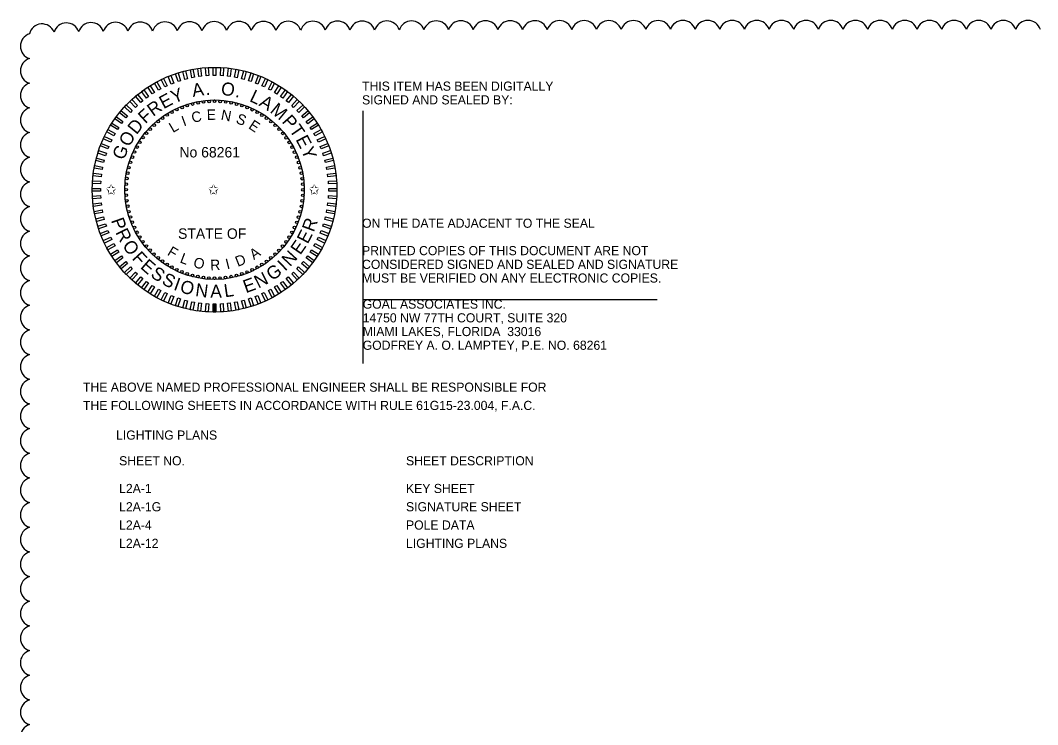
# Model space of a CAD drawing. Extents: x -811 to 10319, y -2309 to 9962.
# Drawn here: x -810.98 to -803.18, y -2279.1 to -2273.71 of the extents above; entities that cross this region are included whole.
import ezdxf

# ---------------------------------------------------------------- set-up
doc = ezdxf.new("R2010")
doc.units = 0
for name, color, linetype in [('AdhocPoint_dp', 7, 'Continuous'), ('PlotBorder_dp', 7, 'Continuous'), ('ScratchEle_dp', 7, 'Continuous'), ('TextMinor', 7, 'Continuous'), ('TextMisc', 7, 'Continuous'), ('TextShtNo', 7, 'Continuous')]:
    doc.layers.add(name, color=color, linetype=linetype)

msp = doc.modelspace()

# ---------------------------------------------------------------- linework, layer by layer
at = {"layer": 'AdhocPoint_dp'}
for p, q in [((-808.3546, -2274.4022), (-808.3546, -2276.337)), ((-808.3546, -2275.847), (-806.0979, -2275.847))]:
    msp.add_line(p, q, dxfattribs=at)
at = {"layer": 'ScratchEle_dp'}
for centre, radius, start, end in [((-810.0588, -2273.8204), 0.0991, 17.94243, 162.94243), ((-809.8699, -2273.819), 0.0991, 17.8789, 162.8789), ((-809.6809, -2273.8179), 0.0991, 17.83076, 162.83076), ((-809.4919, -2273.8168), 0.0991, 17.79266, 162.79266), ((-809.3029, -2273.8159), 0.0991, 17.76151, 162.76151), ((-809.1139, -2273.8151), 0.0991, 17.73544, 162.73544), ((-808.9249, -2273.8144), 0.0991, 17.7132, 162.7132), ((-808.736, -2273.8137), 0.0991, 17.69393, 162.69393), ((-808.547, -2273.8131), 0.0991, 17.67702, 162.67702), ((-808.358, -2273.8125), 0.0991, 17.66204, 162.66204), ((-808.169, -2273.812), 0.0991, 17.64863, 162.64863), ((-807.98, -2273.8115), 0.0991, 17.63655, 162.63655), ((-807.791, -2273.8111), 0.0991, 17.62558, 162.62558), ((-807.602, -2273.8107), 0.0991, 17.61556, 162.61556), ((-807.413, -2273.8104), 0.0991, 17.60637, 162.60637), ((-807.224, -2273.81), 0.0991, 17.5979, 162.5979), ((-807.035, -2273.8097), 0.0991, 17.59006, 162.59006), ((-806.846, -2273.8094), 0.0991, 17.58277, 162.58277), ((-806.657, -2273.8092), 0.0991, 17.57597, 162.57597), ((-806.468, -2273.8089), 0.0991, 17.56961, 162.56961), ((-806.279, -2273.8087), 0.0991, 17.56364, 162.56364), ((-806.09, -2273.8085), 0.0991, 17.55803, 162.55803), ((-805.901, -2273.8083), 0.0991, 17.55274, 162.55274), ((-805.712, -2273.8082), 0.0991, 17.54774, 162.54774), ((-805.523, -2273.808), 0.0991, 17.54301, 162.54301), ((-805.334, -2273.8079), 0.0991, 17.53852, 162.53852), ((-805.145, -2273.8077), 0.0991, 17.53425, 162.53425), ((-804.956, -2273.8076), 0.0991, 17.53018, 162.53018), ((-804.767, -2273.8075), 0.0991, 17.52631, 162.52631), ((-804.578, -2273.8075), 0.0991, 17.52261, 162.52261), ((-804.389, -2273.8074), 0.0991, 17.51907, 162.51907), ((-804.2, -2273.8073), 0.0991, 17.51569, 162.51569), ((-804.011, -2273.8073), 0.0991, 17.51244, 162.51244), ((-803.822, -2273.8073), 0.0991, 17.50933, 162.50933), ((-803.633, -2273.8072), 0.0991, 17.50633, 162.50633), ((-803.444, -2273.8072), 0.0991, 17.50345, 162.50345), ((-803.2551, -2273.8072), 0.0991, 17.50077, 162.50077), ((-810.8128, -2273.8348), 0.0992, 21.52097, 166.52097), ((-810.6255, -2273.8267), 0.0991, 18.44241, 163.44241), ((-810.4367, -2273.824), 0.0991, 18.17187, 163.17187), ((-810.2478, -2273.822), 0.0991, 18.03188, 163.03188), ((-810.8794, -2273.9061), 0.099, 107.5, 252.5), ((-810.8794, -2274.095), 0.0991, 107.5, 252.5), ((-810.8794, -2274.2841), 0.0991, 107.5, 252.5), ((-810.8794, -2274.4731), 0.0991, 107.5, 252.5), ((-810.8794, -2274.6621), 0.0991, 107.5, 252.5), ((-810.8794, -2274.8511), 0.0991, 107.5, 252.5), ((-810.8794, -2275.0401), 0.0991, 107.5, 252.5), ((-810.8794, -2275.2291), 0.0991, 107.5, 252.5), ((-810.8794, -2275.4181), 0.0991, 107.5, 252.5), ((-810.8794, -2275.6071), 0.0991, 107.5, 252.5), ((-810.8794, -2275.7961), 0.0991, 107.5, 252.5), ((-810.8794, -2275.9851), 0.0991, 107.5, 252.5), ((-810.8794, -2276.1741), 0.0991, 107.5, 252.5), ((-810.8794, -2276.3631), 0.0991, 107.5, 252.5), ((-810.8794, -2276.5521), 0.0991, 107.5, 252.5), ((-810.8794, -2276.7411), 0.0991, 107.5, 252.5), ((-810.8794, -2276.9301), 0.0991, 107.5, 252.5), ((-810.8794, -2277.1191), 0.0991, 107.5, 252.5), ((-810.8794, -2277.3081), 0.0991, 107.5, 252.5), ((-810.8794, -2277.4971), 0.0991, 107.5, 252.5), ((-810.8794, -2277.6861), 0.0991, 107.5, 252.5), ((-810.8794, -2277.8751), 0.0991, 107.5, 252.5), ((-810.8794, -2278.0641), 0.0991, 107.5, 252.5), ((-810.8794, -2278.2531), 0.0991, 107.5, 252.5), ((-810.8794, -2278.4421), 0.0991, 107.50047, 252.50047), ((-810.8794, -2278.6311), 0.0991, 107.52584, 252.52584), ((-810.8792, -2278.82), 0.0991, 107.56719, 252.56719), ((-810.8789, -2279.009), 0.0991, 107.61129, 252.61129), ((-810.8785, -2279.198), 0.0991, 107.65843, 252.65843)]:
    msp.add_arc(centre, radius, start, end, dxfattribs=at)
at = {"layer": 'TextMinor'}
for radius in [0.9375, 0.6875]:
    msp.add_circle((-809.4901, -2275.0057), radius, dxfattribs=at)
at = {"layer": 'TextShtNo'}
for p, q in [((-809.5001, -2275.9432), (-809.5003, -2275.8807)), ((-809.4901, -2275.9432), (-809.4903, -2275.8807)), ((-809.4801, -2275.9431), (-809.4803, -2275.8806))]:
    msp.add_line(p, q, dxfattribs=at)
for points in [[(-809.7508, -2274.1703), (-809.77, -2274.1765), (-809.7893, -2274.1172), (-809.7701, -2274.1109)], [(-809.6979, -2274.1556), (-809.7174, -2274.1606), (-809.7329, -2274.1001), (-809.7134, -2274.0951)], [(-809.6441, -2274.1442), (-809.6639, -2274.148), (-809.6756, -2274.0867), (-809.6558, -2274.0829)], [(-809.5897, -2274.1362), (-809.6097, -2274.1388), (-809.6175, -2274.0768), (-809.5975, -2274.0743)], [(-809.5349, -2274.1317), (-809.555, -2274.133), (-809.559, -2274.0707), (-809.5388, -2274.0694)], [(-809.4799, -2274.1306), (-809.5001, -2274.1306), (-809.5001, -2274.0682), (-809.4799, -2274.0682)], [(-809.425, -2274.133), (-809.4452, -2274.1317), (-809.4412, -2274.0694), (-809.4211, -2274.0707)], [(-809.3703, -2274.1388), (-809.3904, -2274.1363), (-809.3825, -2274.0743), (-809.3625, -2274.0768)], [(-809.3161, -2274.148), (-809.336, -2274.1442), (-809.3243, -2274.0829), (-809.3044, -2274.0867)], [(-809.2626, -2274.1606), (-809.2822, -2274.1556), (-809.2667, -2274.0951), (-809.2471, -2274.1002)], [(-809.21, -2274.1766), (-809.2292, -2274.1704), (-809.2099, -2274.111), (-809.1907, -2274.1172)], [(-809.9027, -2274.2339), (-809.9204, -2274.2437), (-809.9505, -2274.189), (-809.9328, -2274.1792)], [(-809.8535, -2274.2096), (-809.8717, -2274.2182), (-809.8983, -2274.1617), (-809.8801, -2274.1531)], [(-809.8028, -2274.1883), (-809.8215, -2274.1957), (-809.8445, -2274.1377), (-809.8258, -2274.1303)], [(-809.1585, -2274.1958), (-809.1773, -2274.1884), (-809.1543, -2274.1303), (-809.1355, -2274.1378)], [(-809.1083, -2274.2182), (-809.1266, -2274.2096), (-809.1, -2274.1531), (-809.0817, -2274.1617)], [(-809.0596, -2274.2438), (-809.0773, -2274.234), (-809.0473, -2274.1793), (-809.0296, -2274.189)], [(-809.9962, -2274.2917), (-810.0125, -2274.3036), (-810.0492, -2274.2531), (-810.0329, -2274.2412)], [(-809.9504, -2274.2614), (-809.9674, -2274.2722), (-810.0009, -2274.2195), (-809.9838, -2274.2087)], [(-809.0127, -2274.2723), (-809.0297, -2274.2615), (-808.9962, -2274.2088), (-808.9792, -2274.2196)], [(-808.9675, -2274.3037), (-808.9839, -2274.2919), (-808.9472, -2274.2413), (-808.9308, -2274.2532)], [(-810.0817, -2274.3608), (-810.0964, -2274.3746), (-810.1391, -2274.3291), (-810.1244, -2274.3153)], [(-810.04, -2274.3249), (-810.0556, -2274.3378), (-810.0954, -2274.2897), (-810.0798, -2274.2768)], [(-808.9245, -2274.3379), (-808.9401, -2274.3251), (-808.9003, -2274.2769), (-808.8847, -2274.2898)], [(-808.8837, -2274.3748), (-808.8984, -2274.3609), (-808.8557, -2274.3154), (-808.8409, -2274.3292)], [(-810.1578, -2274.44), (-810.1707, -2274.4556), (-810.2188, -2274.4158), (-810.206, -2274.4002)], [(-810.121, -2274.3992), (-810.1348, -2274.4139), (-810.1803, -2274.3712), (-810.1665, -2274.3565)], [(-808.8453, -2274.4141), (-808.8591, -2274.3994), (-808.8136, -2274.3566), (-808.7998, -2274.3713)], [(-808.8094, -2274.4557), (-808.8223, -2274.4402), (-808.7742, -2274.4004), (-808.7613, -2274.4159)], [(-810.2235, -2274.5282), (-810.2343, -2274.5452), (-810.287, -2274.5118), (-810.2762, -2274.4947)], [(-810.192, -2274.4831), (-810.2039, -2274.4994), (-810.2544, -2274.4627), (-810.2426, -2274.4464)], [(-808.7762, -2274.4996), (-808.7881, -2274.4832), (-808.7376, -2274.4465), (-808.7257, -2274.4629)], [(-808.7458, -2274.5454), (-808.7567, -2274.5283), (-808.7039, -2274.4949), (-808.6931, -2274.5119)], [(-810.252, -2274.5752), (-810.2617, -2274.5929), (-810.3164, -2274.5628), (-810.3067, -2274.5451)], [(-808.7184, -2274.593), (-808.7281, -2274.5753), (-808.6734, -2274.5453), (-808.6637, -2274.5629)], [(-810.3, -2274.6741), (-810.3074, -2274.6928), (-810.3654, -2274.6698), (-810.358, -2274.6511)], [(-810.2775, -2274.6239), (-810.2861, -2274.6421), (-810.3426, -2274.6155), (-810.334, -2274.5973)], [(-808.694, -2274.6423), (-808.7026, -2274.624), (-808.6461, -2274.5974), (-808.6375, -2274.6157)], [(-808.6728, -2274.693), (-808.6802, -2274.6742), (-808.6222, -2274.6512), (-808.6147, -2274.67)], [(-810.3192, -2274.7256), (-810.3254, -2274.7448), (-810.3848, -2274.7255), (-810.3786, -2274.7063)], [(-808.6548, -2274.7449), (-808.661, -2274.7257), (-808.6016, -2274.7064), (-808.5954, -2274.7256)], [(-810.3351, -2274.7782), (-810.3401, -2274.7977), (-810.4006, -2274.7822), (-810.3956, -2274.7626)], [(-808.64, -2274.7979), (-808.6451, -2274.7784), (-808.5846, -2274.7628), (-808.5796, -2274.7824)], [(-810.357, -2274.8859), (-810.3595, -2274.9059), (-810.4214, -2274.8981), (-810.4189, -2274.878)], [(-810.3477, -2274.8317), (-810.3515, -2274.8515), (-810.4129, -2274.8398), (-810.4091, -2274.82)], [(-808.6287, -2274.8517), (-808.6325, -2274.8319), (-808.5711, -2274.8202), (-808.5673, -2274.84)], [(-808.6207, -2274.9061), (-808.6232, -2274.8861), (-808.5613, -2274.8782), (-808.5588, -2274.8983)], [(-810.3628, -2274.9405), (-810.364, -2274.9607), (-810.4264, -2274.9568), (-810.4251, -2274.9366)], [(-808.6162, -2274.9609), (-808.6174, -2274.9407), (-808.5551, -2274.9368), (-808.5539, -2274.957)], [(-810.3651, -2274.9955), (-810.3651, -2275.0156), (-810.4276, -2275.0156), (-810.4276, -2274.9955)], [(-808.6151, -2275.0158), (-808.6151, -2274.9957), (-808.5526, -2274.9957), (-808.5526, -2275.0158)], [(-810.3641, -2275.0504), (-810.3628, -2275.0706), (-810.4251, -2275.0745), (-810.4264, -2275.0543)], [(-810.3595, -2275.1052), (-810.357, -2275.1252), (-810.4189, -2275.1331), (-810.4215, -2275.113)], [(-808.6233, -2275.1254), (-808.6207, -2275.1054), (-808.5588, -2275.1132), (-808.5613, -2275.1333)], [(-808.6175, -2275.0708), (-808.6162, -2275.0506), (-808.5539, -2275.0545), (-808.5551, -2275.0747)], [(-810.3516, -2275.1596), (-810.3478, -2275.1794), (-810.4091, -2275.1911), (-810.4129, -2275.1713)], [(-808.6325, -2275.1796), (-808.6287, -2275.1598), (-808.5674, -2275.1715), (-808.5712, -2275.1913)], [(-810.3402, -2275.2134), (-810.3352, -2275.2329), (-810.3956, -2275.2485), (-810.4007, -2275.2289)], [(-810.3255, -2275.2664), (-810.3192, -2275.2856), (-810.3786, -2275.3049), (-810.3849, -2275.2857)], [(-808.6611, -2275.2857), (-808.6548, -2275.2665), (-808.5954, -2275.2858), (-808.6017, -2275.305)], [(-808.6451, -2275.2331), (-808.6401, -2275.2136), (-808.5796, -2275.2291), (-808.5846, -2275.2487)], [(-810.3074, -2275.3183), (-810.3, -2275.3371), (-810.3581, -2275.3601), (-810.3655, -2275.3413)], [(-808.6803, -2275.3372), (-808.6729, -2275.3185), (-808.6148, -2275.3415), (-808.6222, -2275.3602)], [(-810.2862, -2275.369), (-810.2776, -2275.3873), (-810.3341, -2275.4139), (-810.3427, -2275.3956)], [(-810.2618, -2275.4183), (-810.2521, -2275.436), (-810.3068, -2275.466), (-810.3165, -2275.4484)], [(-808.7282, -2275.4361), (-808.7185, -2275.4184), (-808.6638, -2275.4485), (-808.6735, -2275.4662)], [(-808.7027, -2275.3874), (-808.6941, -2275.3692), (-808.6376, -2275.3958), (-808.6462, -2275.414)], [(-810.2344, -2275.4659), (-810.2236, -2275.483), (-810.2763, -2275.5164), (-810.2871, -2275.4994)], [(-810.204, -2275.5117), (-810.1922, -2275.5281), (-810.2427, -2275.5648), (-810.2545, -2275.5484)], [(-808.7882, -2275.5282), (-808.7763, -2275.5119), (-808.7258, -2275.5486), (-808.7377, -2275.5649)], [(-808.7568, -2275.4831), (-808.7459, -2275.4661), (-808.6932, -2275.4995), (-808.704, -2275.5166)], [(-810.1708, -2275.5556), (-810.158, -2275.5711), (-810.2061, -2275.6109), (-810.2189, -2275.5954)], [(-808.8224, -2275.5713), (-808.8095, -2275.5557), (-808.7614, -2275.5955), (-808.7743, -2275.6111)], [(-810.135, -2275.5972), (-810.1211, -2275.6119), (-810.1667, -2275.6547), (-810.1805, -2275.64)], [(-810.0965, -2275.6365), (-810.0818, -2275.6504), (-810.1246, -2275.6959), (-810.1393, -2275.6821)], [(-808.8985, -2275.6505), (-808.8838, -2275.6367), (-808.8411, -2275.6822), (-808.8558, -2275.696)], [(-808.8592, -2275.6121), (-808.8454, -2275.5974), (-808.7999, -2275.6401), (-808.8137, -2275.6548)], [(-810.0557, -2275.6734), (-810.0402, -2275.6862), (-810.08, -2275.7344), (-810.0955, -2275.7215)], [(-810.0127, -2275.7076), (-809.9964, -2275.7194), (-810.0331, -2275.77), (-810.0494, -2275.7581)], [(-809.9676, -2275.739), (-809.9505, -2275.7498), (-809.984, -2275.8025), (-810.001, -2275.7917)], [(-809.0299, -2275.7499), (-809.0128, -2275.7391), (-808.9794, -2275.7918), (-808.9964, -2275.8026)], [(-808.984, -2275.7196), (-808.9677, -2275.7077), (-808.931, -2275.7582), (-808.9473, -2275.7701)], [(-808.9402, -2275.6864), (-808.9246, -2275.6735), (-808.8848, -2275.7216), (-808.9004, -2275.7345)], [(-809.9206, -2275.7675), (-809.9029, -2275.7773), (-809.933, -2275.832), (-809.9507, -2275.8223)], [(-809.8719, -2275.7931), (-809.8536, -2275.8017), (-809.8802, -2275.8582), (-809.8985, -2275.8496)], [(-809.8217, -2275.8155), (-809.8029, -2275.8229), (-809.8259, -2275.881), (-809.8447, -2275.8735)], [(-809.1775, -2275.823), (-809.1587, -2275.8156), (-809.1357, -2275.8736), (-809.1545, -2275.881)], [(-809.1268, -2275.8017), (-809.1085, -2275.7931), (-809.0819, -2275.8496), (-809.1002, -2275.8582)], [(-809.0775, -2275.7774), (-809.0598, -2275.7676), (-809.0297, -2275.8223), (-809.0474, -2275.8321)], [(-809.7702, -2275.8347), (-809.751, -2275.8409), (-809.7703, -2275.9003), (-809.7895, -2275.8941)], [(-809.7176, -2275.8507), (-809.698, -2275.8557), (-809.7136, -2275.9162), (-809.7331, -2275.9111)], [(-809.6641, -2275.8633), (-809.6443, -2275.8671), (-809.656, -2275.9284), (-809.6758, -2275.9246)], [(-809.6099, -2275.8725), (-809.5899, -2275.875), (-809.5977, -2275.937), (-809.6177, -2275.9345)], [(-809.5552, -2275.8783), (-809.5351, -2275.8796), (-809.539, -2275.9419), (-809.5591, -2275.9406)], [(-809.5003, -2275.8807), (-809.4801, -2275.8807), (-809.4801, -2275.9431), (-809.5003, -2275.9431)], [(-809.4453, -2275.8796), (-809.4252, -2275.8783), (-809.4213, -2275.9406), (-809.4414, -2275.9419)], [(-809.3906, -2275.8751), (-809.3705, -2275.8725), (-809.3627, -2275.9345), (-809.3827, -2275.937)], [(-809.3362, -2275.8671), (-809.3163, -2275.8633), (-809.3046, -2275.9246), (-809.3245, -2275.9284)], [(-809.2824, -2275.8557), (-809.2628, -2275.8507), (-809.2473, -2275.9112), (-809.2668, -2275.9162)], [(-809.2294, -2275.841), (-809.2102, -2275.8348), (-809.1909, -2275.8941), (-809.2101, -2275.9004)]]:
    msp.add_lwpolyline(points, close=True, dxfattribs=at)
for centre in [(-809.6581, -2274.3493), (-809.6165, -2274.3401), (-809.5745, -2274.3335), (-809.5321, -2274.3295), (-809.4896, -2274.3282), (-809.447, -2274.3296), (-809.4046, -2274.3336), (-809.3626, -2274.3403), (-809.3211, -2274.3496), (-809.8526, -2274.4333), (-809.816, -2274.4117), (-809.7781, -2274.3924), (-809.739, -2274.3755), (-809.6989, -2274.3612), (-809.2802, -2274.3615), (-809.2402, -2274.376), (-809.2012, -2274.3929), (-809.1633, -2274.4123), (-809.1266, -2274.4339), (-809.9535, -2274.5114), (-809.9215, -2274.4833), (-809.8879, -2274.4572), (-809.0915, -2274.4579), (-809.0578, -2274.484), (-809.0259, -2274.5122), (-810.0118, -2274.5734), (-809.9836, -2274.5415), (-808.9959, -2274.5423), (-808.9678, -2274.5742), (-810.0618, -2274.6422), (-810.0379, -2274.607), (-808.9417, -2274.6079), (-808.9178, -2274.6431), (-810.1029, -2274.7167), (-810.0835, -2274.6788), (-808.8962, -2274.6798), (-808.8769, -2274.7177), (-810.1343, -2274.7958), (-810.1198, -2274.7557), (-808.86, -2274.7568), (-808.8456, -2274.7968), (-810.1555, -2274.8782), (-810.1462, -2274.8366), (-808.8338, -2274.8377), (-808.8245, -2274.8793), (-810.1662, -2274.9625), (-810.1622, -2274.9202), (-808.8179, -2274.9213), (-808.814, -2274.9637), (-810.1676, -2275.0051), (-810.1663, -2275.0476), (-808.814, -2275.0488), (-808.8126, -2275.0062), (-810.1623, -2275.09), (-810.1557, -2275.132), (-808.8248, -2275.1331), (-808.8181, -2275.0911), (-810.1464, -2275.1736), (-808.8341, -2275.1747), (-810.1346, -2275.2145), (-810.1202, -2275.2545), (-808.8604, -2275.2556), (-808.846, -2275.2155), (-810.1033, -2275.2936), (-810.0841, -2275.3315), (-810.0624, -2275.3682), (-808.9184, -2275.3691), (-808.8967, -2275.3325), (-808.8774, -2275.2946), (-810.0385, -2275.4034), (-810.0125, -2275.4371), (-808.9685, -2275.4379), (-808.9424, -2275.4043), (-809.9844, -2275.469), (-809.9543, -2275.4991), (-809.0268, -2275.4999), (-808.9967, -2275.4698), (-809.9224, -2275.5273), (-809.8888, -2275.5534), (-809.8536, -2275.5774), (-809.817, -2275.599), (-809.1642, -2275.5996), (-809.1276, -2275.578), (-809.0924, -2275.5541), (-809.0587, -2275.528), (-809.7791, -2275.6184), (-809.74, -2275.6353), (-809.7, -2275.6498), (-809.6591, -2275.6617), (-809.6176, -2275.671), (-809.5756, -2275.6777), (-809.5332, -2275.6817), (-809.4481, -2275.6818), (-809.4058, -2275.6778), (-809.3637, -2275.6712), (-809.3222, -2275.662), (-809.2813, -2275.6501), (-809.2412, -2275.6358), (-809.2022, -2275.6189), (-809.4901, -2275.6832)]:
    msp.add_circle(centre, 0.01, dxfattribs=at)

# ---------------------------------------------------------------- texts
at = {"layer": 'PlotBorder_dp'}
for s, p in [('THIS ITEM HAS BEEN DIGITALLY', (-808.3596, -2274.2471)), ('SIGNED AND SEALED BY:', (-808.3596, -2274.3521)), ('ON THE DATE ADJACENT TO THE SEAL', (-808.3596, -2275.2971)), ('PRINTED COPIES OF THIS DOCUMENT ARE NOT ', (-808.3596, -2275.5071)), ('CONSIDERED SIGNED AND SEALED AND SIGNATURE ', (-808.3596, -2275.6121)), ('MUST BE VERIFIED ON ANY ELECTRONIC COPIES.', (-808.3596, -2275.7171)), ('GOAL ASSOCIATES INC.', (-808.3546, -2275.917)), ('14750 NW 77TH COURT, SUITE 320', (-808.3546, -2276.022)), ('MIAMI LAKES, FLORIDA  33016', (-808.3546, -2276.127)), ('GODFREY A. O. LAMPTEY, P.E. NO. 68261', (-808.3546, -2276.232)), ('THE ABOVE NAMED PROFESSIONAL ENGINEER SHALL BE RESPONSIBLE FOR ', (-810.4987, -2276.5531)), ('THE FOLLOWING SHEETS IN ACCORDANCE WITH RULE 61G15-23.004, F.A.C.', (-810.4987, -2276.6931)), ('LIGHTING PLANS', (-810.245, -2276.9201))]:
    msp.add_text(s, height=0.07, dxfattribs=at).set_placement(p)
at = {"layer": 'TextMisc'}
for s, p in [('SHEET NO.', (-810.2215, -2277.1171)), ('SHEET DESCRIPTION', (-808.0226, -2277.1171)), ('L2A-1', (-810.2215, -2277.3293)), ('KEY SHEET', (-808.0226, -2277.3293)), ('L2A-1G', (-810.2215, -2277.4693)), ('SIGNATURE SHEET', (-808.0226, -2277.4693)), ('L2A-4', (-810.2215, -2277.6093)), ('POLE DATA', (-808.0226, -2277.6093)), ('L2A-12', (-810.2215, -2277.7493)), ('LIGHTING PLANS', (-808.0226, -2277.7493))]:
    msp.add_text(s, height=0.07, dxfattribs=at).set_placement(p)
at = {"layer": 'TextShtNo'}
for s, height, rotation, p in [('A', 0.1, 8.80884, (-809.6551, -2274.295)), ('O', 0.1, 352.18771, (-809.4449, -2274.2775)), ('E', 0.1, 28.10553, (-809.8806, -2274.3895)), ('Y', 0.1, 21.06329, (-809.8021, -2274.3462)), ('.', 0.1, 1.04184, (-809.5575, -2274.2793)), ('L', 0.1, 334.67271, (-809.2279, -2274.3249)), ('R', 0.1, 35.92688, (-809.9609, -2274.4483)), ('.', 0.1, 343.52684, (-809.3358, -2274.2926)), ('A', 0.1, 328.40959, (-809.1552, -2274.3576)), ('M', 0.1, 320.6426, (-809.0707, -2274.4088)), ('F', 0.1, 42.37723, (-810.0205, -2274.5047)), ('C', 0.08, 12.20255, (-809.6579, -2274.494)), ('E', 0.08, 0.41861, (-809.5498, -2274.4706)), ('N', 0.08, 349.29143, (-809.4455, -2274.4691)), ('D', 0.1, 50.8569, (-810.0885, -2274.5884)), ('L', 0.08, 30.40215, (-809.8093, -2274.572)), ('I', 0.08, 20.01168, (-809.7258, -2274.5216)), ('S', 0.08, 337.02207, (-809.3325, -2274.4909)), ('E', 0.08, 325.86633, (-809.2358, -2274.5311)), ('P', 0.1, 311.19658, (-808.9784, -2274.4857)), ('T', 0.1, 304.45632, (-808.9209, -2274.5494)), ('O', 0.1, 59.51777, (-810.1446, -2274.6833)), ('E', 0.1, 297.63152, (-808.8707, -2274.6202)), ('G', 0.1, 68.0518, (-810.1851, -2274.784)), ('Y', 0.1, 290.58928, (-808.8281, -2274.6991)), ('P', 0.1, 289.40551, (-810.2848, -2275.2402)), ('R', 0.1, 69.5134, (-808.7299, -2275.3354)), ('R', 0.1, 296.14576, (-810.2518, -2275.3319)), ('E', 0.1, 62.47116, (-808.7761, -2275.4261)), ('O', 0.1, 303.96711, (-810.2003, -2275.4325)), ('E', 0.1, 55.42892, (-808.833, -2275.5104)), ('F', 0.1, 312.62798, (-810.1279, -2275.5346)), ('F', 0.08, 328.72408, (-809.8582, -2275.5022)), ('L', 0.08, 339.29159, (-809.7609, -2275.5613)), ('D', 0.08, 22.01279, (-809.312, -2275.5976)), ('A', 0.08, 34.49917, (-809.1883, -2275.5451)), ('N', 0.1, 47.17876, (-808.9123, -2275.5995)), ('E', 0.1, 319.07833, (-810.0645, -2275.6029)), ('O', 0.08, 349.68206, (-809.6562, -2275.601)), ('R', 0.08, 2.33977, (-809.5217, -2275.623)), ('I', 0.08, 14.20366, (-809.3941, -2275.6163)), ('G', 0.1, 35.11153, (-809.0492, -2275.7072)), ('I', 0.1, 43.64556, (-808.9499, -2275.634)), ('S', 0.1, 326.12056, (-809.9869, -2275.6688)), ('S', 0.1, 333.193, (-809.9015, -2275.7249)), ('N', 0.1, 26.86136, (-809.1544, -2275.7632)), ('I', 0.1, 340.26543, (-809.8098, -2275.7701)), ('O', 0.1, 343.79863, (-809.7621, -2275.7883)), ('N', 0.1, 352.45949, (-809.6411, -2275.8204)), ('A', 0.1, 0.70966, (-809.5227, -2275.8336)), ('L', 0.1, 8.47665, (-809.4105, -2275.8304)), ('E', 0.1, 19.81912, (-809.2498, -2275.7986))]:
    msp.add_text(s, height=height, rotation=rotation, dxfattribs=at).set_placement(p)
for s, p in [('No 68261', (-809.7591, -2274.7584)), ('✩', (-810.3251, -2275.0436)), ('✩', (-809.5404, -2275.0436)), ('✩', (-808.7685, -2275.0436)), ('STATE OF', (-809.7698, -2275.3818))]:
    msp.add_text(s, height=0.08, dxfattribs=at).set_placement(p)

doc.saveas('drawing.dxf')
